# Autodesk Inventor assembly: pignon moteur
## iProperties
Author: chr
Created: 2002-03
Part Number: pignon moteur
Document SubType Name: Assemblage
Designer: chr
Control State: 0
Master: False
Checked Out: False
PropertySet Name: Design Tracking Control
Shininess: 41.0
Angle Display Precision: 2
Document Length Units: 11269
Document Angle Units: 11283
Document Time Units: 11279
Document Mass Units: 11290
Document Length Units Precision: 3
Document Angle Units Precision: 2
Compacted: False
PropertySet Name: _Private Model Information
Density: 0.0
Volumn: 0.0
Area: 0.0
PropertySet Name: Model Information
